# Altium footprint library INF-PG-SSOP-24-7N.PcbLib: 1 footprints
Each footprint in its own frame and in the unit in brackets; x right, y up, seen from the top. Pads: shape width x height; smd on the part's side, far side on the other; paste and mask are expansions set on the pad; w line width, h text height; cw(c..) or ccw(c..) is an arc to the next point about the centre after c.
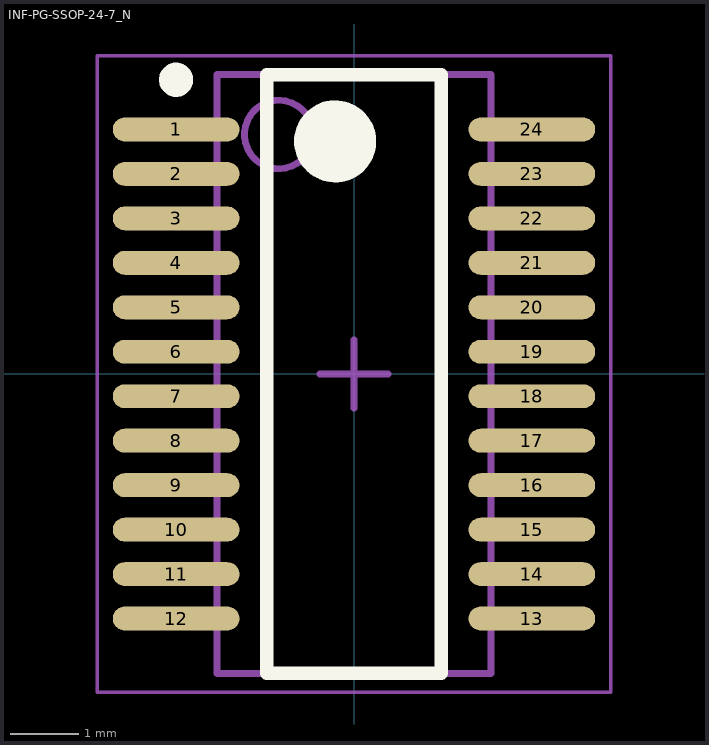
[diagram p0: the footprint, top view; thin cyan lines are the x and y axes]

## INF-PG-SSOP-24-7_N [mm] "SOP, 24-Leads, Body 8.65x3.9mm, Pitch 0.65mm, IPC Medium Density"
height 1.75
pads (24):
  oval 1.85x0.35 smd: 1(-2.6,3.575) 2(-2.6,2.925) 3(-2.6,2.275) 4(-2.6,1.625) 5(-2.6,0.975) 6(-2.6,0.325) 7(-2.6,-0.325) 8(-2.6,-0.975) 9(-2.6,-1.625) 10(-2.6,-2.275) 11(-2.6,-2.925) 12(-2.6,-3.575) 13(2.6,-3.575) 14(2.6,-2.925) 15(2.6,-2.275) 16(2.6,-1.625) 17(2.6,-0.975) 18(2.6,-0.325) 19(2.6,0.325) 20(2.6,0.975) 21(2.6,1.625) 22(2.6,2.275) 23(2.6,2.925) 24(2.6,3.575)
Top Overlay:
  circle w0.6: c-0.275,3.4 r0.3
  circle w0.25: c-2.6,4.3 r0.125
  lines w0.2: -1.275,-4.375 1.275,-4.375 1.275,4.375 -1.275,4.375 -1.275,-4.375
Mechanical 13:
  circle w0.1: c-1.1,3.5 r0.5
  lines w0.1: -2,-4.375 2,-4.375 2,4.375 -2,4.375 -2,-4.375
Mechanical 15:
  lines w0.05: -3.75,-4.65 3.75,-4.65 3.75,4.65 -3.75,4.65 -3.75,-4.65
  lines w0.1: -0.5,0 0.5,0 ; 0,-0.5 0,0.5
3D body: height 1.75, standoff 0.11, extent -2,-4.375 2,4.375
